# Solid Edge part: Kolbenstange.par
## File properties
Username: bmolnar
Dokumentum tartalom típus: 0
Author: bmolnar
Last saved by: bmolnar
Revision: 82
Sűrűség: 0,000 kg/m^3
Pontosság: 0,990
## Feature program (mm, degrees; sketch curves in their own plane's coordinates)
base feature "unnamed BaseFeature 1"
sketch for "unnamed Protrusion 1" plane through (18, 0, 0) normal (1, 0, 0) x-axis (0, 1, 0)
  circle centre (0, 0) radius 6
extrude "unnamed Protrusion 1" add finite 15.7 along +normal
sketch for "Kihúzás_2" plane through (18, 0, 0) normal (1, 0, 0) x-axis (0, 1, 0)
  circle centre (0, 0) radius 6
extrude "Kihúzás_2" add finite 6.45 along -normal
sketch for "Furat_1" plane through (-35, 0, 0) normal (-1, 0, 0) x-axis (0, -1, 0)
  hole centre (0, 0) bore radius 1.2295
hole "Furat_1" nominal diameter 3 finite  VBottomAngle = 118 deg; ThreadDepth = 7 mm
chamfer "Letörés_1" setback 0.3  SetBackValue2 = 45 deg
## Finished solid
Body 1: solid body, 15 faces, 23 edges, 10 vertices.
  Faces by surface: plane 7, cone 4, cylinder 4
  Edges by curve: circle 11, line 6, spline 4, ellipse 2
Bounding box of the edges (mm): 68.700 x 12.000 x 12.000, from (-35, -6, -6) to (33.7, 6, 6).
Cylindrical faces by radius (mm): R1.2295 x2, R3 x1, R6 x1
Conical faces (half-angle, radius in mm at the cone's reference point): 45 deg R1.5295 x1, 45 deg R2.75 x2, 59 deg R1.2295 x1
Planar faces by outward normal: +x 1, +z 1, -x 2, -z 1, oblique 2
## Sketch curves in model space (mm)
circle centre (18, 0, 0) radius 6
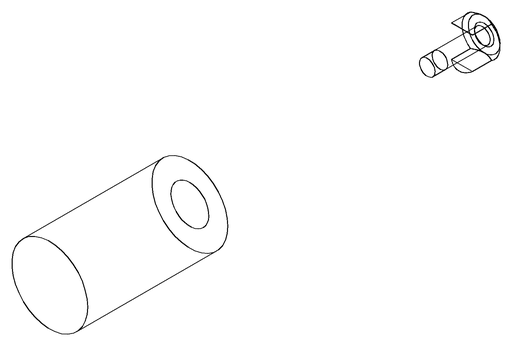
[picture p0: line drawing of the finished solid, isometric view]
